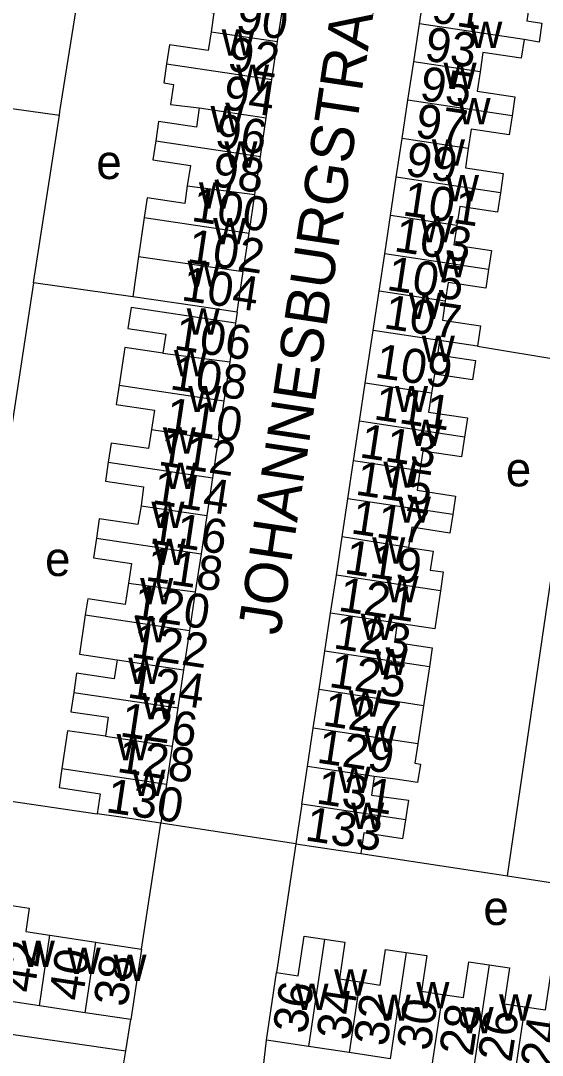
# Model space of a CAD drawing. Extents: x 163012 to 165277, y 382513 to 383987.
# Drawn here: x 163589 to 163650, y 383224 to 383344.9 of the extents above; entities that cross this region are included whole.
import ezdxf

# ---------------------------------------------------------------- set-up
doc = ezdxf.new("R2010")
doc.units = 0
for name, color, linetype in [('BLT_Basislijn', 7, 'Continuous'), ('BLT_Bebouwing', 7, 'Continuous'), ('BLT_Centroide', 7, 'Continuous'), ('BLT_Huisnummer', 7, 'Continuous'), ('BLT_Huisnummer_ tussenligend', 7, 'Continuous'), ('BLT_Onderverdeling_panden', 7, 'Continuous'), ('BLT_Straatnaam', 7, 'Continuous'), ('BLT_Vlakafsluiter', 7, 'Continuous')]:
    doc.layers.add(name, color=color, linetype=linetype)

msp = doc.modelspace()

# ---------------------------------------------------------------- linework, layer by layer
at = {"layer": 'BLT_Basislijn'}
for p, q in [((163578.51, 383335.96), (163593.55, 383333.89)), ((163590.52, 383314.29), (163587.56, 383294.8)), ((163602.12, 383312.65), (163590.52, 383314.29)), ((163614.32, 383310.83), (163614.13, 383309.57)), ((163642.42, 383306.86), (163654.69, 383304.83)), ((163645.91, 383244.93), (163654.69, 383304.83)), ((163581.46, 383254.63), (163597.96, 383252.2)), ((163603.16, 383236.37), (163605.39, 383251.09)), ((163621.19, 383248.7), (163618.94, 383233.65)), ((163628.78, 383247.57), (163645.91, 383244.93)), ((163645.91, 383244.93), (163662.24, 383242.43)), ((163601.31, 383224.5), (163601.91, 383228.14)), ((163617.35, 383222.35), (163617.75, 383225.74)), ((163600.65, 383220.44), (163601.31, 383224.5))]:
    msp.add_line(p, q, dxfattribs=at)
for points in [[(163593.55, 383333.89), (163593.61, 383334.29), (163599.84, 383373.27)], [(163590.52, 383314.29), (163590.56, 383314.53), (163593.55, 383333.89)], [(163553.82, 383235.38), (163553.31, 383231.45), (163601.31, 383224.5)]]:
    msp.add_lwpolyline(points, dxfattribs=at)
at = {"layer": 'BLT_Bebouwing'}
for p, q in [((163635.63, 383344.56), (163636.3, 383349.01)), ((163619.06, 383342.48), (163619.73, 383346.98)), ((163634.96, 383340.11), (163635.63, 383344.56)), ((163618.39, 383338.05), (163619.06, 383342.48)), ((163634.28, 383335.62), (163634.96, 383340.11)), ((163617.72, 383333.55), (163618.39, 383338.05)), ((163633.61, 383331.14), (163634.28, 383335.62)), ((163617.05, 383329.05), (163617.72, 383333.55)), ((163632.93, 383326.63), (163633.61, 383331.14)), ((163616.38, 383324.6), (163617.05, 383329.05)), ((163632.25, 383322.13), (163632.93, 383326.63)), ((163615.71, 383320.09), (163616.38, 383324.6)), ((163631.58, 383317.68), (163632.25, 383322.13)), ((163615.04, 383315.62), (163615.71, 383320.09)), ((163630.92, 383313.29), (163631.58, 383317.68)), ((163614.32, 383310.83), (163615.04, 383315.62)), ((163630.23, 383308.7), (163630.92, 383313.29)), ((163614.13, 383309.57), (163613.45, 383305.03)), ((163629.3, 383302.55), (163630.23, 383308.7)), ((163642.42, 383306.86), (163637.98, 383307.53)), ((163613.45, 383305.03), (163612.77, 383300.48)), ((163628.63, 383298.09), (163629.3, 383302.55)), ((163612.77, 383300.48), (163612.1, 383295.97)), ((163627.93, 383293.48), (163628.63, 383298.09)), ((163612.1, 383295.97), (163611.43, 383291.49)), ((163627.26, 383289.03), (163627.93, 383293.48)), ((163611.43, 383291.49), (163610.77, 383287.07)), ((163626.6, 383284.59), (163627.26, 383289.03)), ((163610.77, 383287.07), (163610.1, 383282.59)), ((163625.92, 383280.09), (163626.6, 383284.59)), ((163610.1, 383282.59), (163609.43, 383278.14)), ((163625.25, 383275.66), (163625.92, 383280.09)), ((163609.43, 383278.14), (163608.76, 383273.62)), ((163624.58, 383271.22), (163625.25, 383275.66)), ((163608.76, 383273.62), (163608.07, 383269.04)), ((163623.91, 383266.75), (163624.58, 383271.22)), ((163608.07, 383269.04), (163607.4, 383264.57)), ((163623.23, 383262.23), (163623.91, 383266.75)), ((163607.4, 383264.57), (163606.74, 383260.11)), ((163636.12, 383264.84), (163635.45, 383260.38)), ((163622.55, 383257.74), (163623.23, 383262.23)), ((163606.74, 383260.11), (163606.07, 383255.67)), ((163621.89, 383253.32), (163622.55, 383257.74)), ((163606.07, 383255.67), (163605.39, 383251.09)), ((163592.44, 383238.01), (163597.8, 383237.19)), ((163603.16, 383236.37), (163601.91, 383228.14)), ((163617.75, 383225.74), (163618.94, 383233.65)), ((163591.2, 383229.75), (163585.85, 383230.56)), ((163596.56, 383228.95), (163591.2, 383229.75)), ((163601.91, 383228.14), (163596.56, 383228.95)), ((163622.65, 383225), (163617.75, 383225.74)), ((163627.42, 383224.28), (163622.65, 383225)), ((163632.21, 383223.56), (163627.42, 383224.28))]:
    msp.add_line(p, q, dxfattribs=at)
for points in [[(163607.44, 383348.82), (163607.09, 383346.52), (163611.61, 383345.85), (163611.28, 383343.64)], [(163644, 383347.85), (163648.55, 383347.23), (163648.19, 383344.9), (163649.93, 383344.64), (163649.64, 383342.42), (163647.86, 383342.72)], [(163611.28, 383343.64), (163610.95, 383341.44), (163606.41, 383342.12), (163606.08, 383339.89)], [(163647.86, 383342.72), (163647.53, 383340.53), (163643.06, 383341.2), (163642.72, 383338.94)], [(163606.08, 383339.89), (163605.74, 383337.65), (163606.88, 383337.48), (163606.53, 383335.13), (163609.9, 383334.72)], [(163642.72, 383338.94), (163642.38, 383336.67), (163646.79, 383336.01), (163646.46, 383333.79)], [(163609.9, 383334.72), (163609.56, 383332.46), (163605.13, 383333.12), (163604.8, 383330.88)], [(163646.46, 383333.79), (163646.12, 383331.57), (163641.69, 383332.24), (163641.35, 383329.97)], [(163604.8, 383330.88), (163604.46, 383328.64), (163608.86, 383327.98), (163608.5, 383325.61)], [(163641.35, 383329.97), (163641.01, 383327.71), (163645.43, 383327.04), (163645.1, 383324.8)], [(163608.5, 383325.61), (163608.2, 383323.57), (163603.79, 383324.23), (163603.44, 383321.93)], [(163645.1, 383324.8), (163644.76, 383322.55), (163640.35, 383323.22), (163640.01, 383320.96)], [(163603.44, 383321.93), (163602.79, 383317.37)], [(163640.01, 383320.96), (163639.67, 383318.71), (163644.05, 383318.05), (163643.71, 383315.85)], [(163602.79, 383317.37), (163602.12, 383312.65)], [(163643.71, 383315.85), (163643.38, 383313.64), (163638.98, 383314.31), (163638.65, 383312.12)], [(163614.32, 383310.83), (163609.38, 383311.57), (163602.12, 383312.65)], [(163614.13, 383309.57), (163609.19, 383310.31), (163601.93, 383311.4), (163601.56, 383308.95), (163605.97, 383308.29), (163605.64, 383306.07)], [(163638.65, 383312.12), (163638.33, 383309.93), (163642.78, 383309.26), (163642.42, 383306.86)], [(163605.64, 383306.07), (163601.19, 383306.73), (163600.52, 383302.31)], [(163637.98, 383307.53), (163637.73, 383305.87), (163642.17, 383305.2), (163641.83, 383302.94), (163637.39, 383303.61), (163637.05, 383301.39)], [(163600.52, 383302.31), (163600.19, 383300.05), (163604.65, 383299.39), (163604.32, 383297.14)], [(163637.05, 383301.39), (163636.71, 383299.17), (163641.25, 383298.48), (163641.17, 383297.99), (163640.89, 383296.25)], [(163604.32, 383297.14), (163603.98, 383294.89), (163599.58, 383295.54), (163599.25, 383293.32)], [(163640.89, 383296.25), (163640.54, 383293.92), (163636.04, 383294.6), (163635.69, 383292.31)], [(163599.25, 383293.32), (163598.92, 383291.09), (163603.39, 383290.42), (163603.1, 383288.22)], [(163635.69, 383292.31), (163635.35, 383290.02), (163639.84, 383289.34), (163639.52, 383287.18)], [(163603.1, 383288.22), (163602.7, 383286.03), (163598.21, 383286.7), (163597.87, 383284.42)], [(163639.52, 383287.18), (163639.19, 383285.02), (163634.73, 383285.7), (163634.37, 383283.33)], [(163597.87, 383284.42), (163597.53, 383282.13), (163601.98, 383281.47), (163601.62, 383279.17)], [(163634.37, 383283.33), (163637.23, 383282.9), (163636.9, 383280.7), (163638.42, 383280.47), (163638.08, 383278.26)], [(163601.62, 383279.17), (163601.24, 383276.67), (163596.85, 383277.33), (163596.57, 383275.45)], [(163638.08, 383278.26), (163637.42, 383273.81), (163633.04, 383274.49)], [(163596.57, 383275.45), (163595.88, 383270.87), (163600.28, 383270.21)], [(163633.04, 383274.49), (163632.7, 383272.26), (163637.14, 383271.6), (163636.81, 383269.38)], [(163600.28, 383270.21), (163599.94, 383267.99), (163595.55, 383268.65), (163595.22, 383266.39)], [(163636.81, 383269.38), (163636.12, 383264.84)], [(163595.22, 383266.39), (163594.88, 383264.14), (163599.26, 383263.49), (163598.92, 383261.28)], [(163598.92, 383261.28), (163594.49, 383261.91), (163593.83, 383257.5)], [(163635.45, 383260.38), (163635.11, 383258.11), (163635.75, 383258.02), (163635.42, 383255.85), (163632.83, 383256.23), (163630.35, 383256.57)], [(163593.83, 383257.5), (163593.5, 383255.27), (163598.32, 383254.55), (163597.96, 383252.2)], [(163630.35, 383256.57), (163630.35, 383256.57), (163630.03, 383254.39), (163634.35, 383253.78), (163634, 383251.49)], [(163621.89, 383253.32), (163621.39, 383250), (163621.19, 383248.7)], [(163605.39, 383251.09), (163600.44, 383251.83), (163597.96, 383252.2)], [(163634, 383251.49), (163633.67, 383249.28), (163629.15, 383249.96), (163628.78, 383247.57)], [(163621.19, 383248.7), (163626.14, 383247.96), (163628.78, 383247.57)], [(163587.09, 383238.83), (163587.47, 383241.56), (163590.02, 383241.17), (163589.61, 383238.44), (163592.44, 383238.01)], [(163618.94, 383233.65), (163621.47, 383233.27), (163622.17, 383237.89), (163624.54, 383237.53)], [(163597.8, 383237.19), (163598.22, 383237.12), (163603.16, 383236.37)], [(163624.54, 383237.53), (163626.92, 383237.18), (163626.29, 383232.89), (163628.66, 383232.54)], [(163628.66, 383232.54), (163631.04, 383232.18), (163631.66, 383236.35), (163634.08, 383235.99)], [(163634.08, 383235.99), (163636.5, 383235.62), (163635.88, 383231.46), (163638.33, 383231.09)], [(163638.33, 383231.09), (163640.77, 383230.72), (163641.41, 383234.91), (163643.8, 383234.55)], [(163643.8, 383234.55), (163646.18, 383234.19), (163645.55, 383229.99), (163647.96, 383229.63)], [(163647.96, 383229.63), (163650.36, 383229.27), (163650.99, 383233.42), (163653.43, 383233.05)]]:
    msp.add_lwpolyline(points, dxfattribs=at)
at = {"layer": 'BLT_Onderverdeling_panden'}
for p, q in [((163647.86, 383342.72), (163635.63, 383344.56)), ((163611.28, 383343.64), (163619.06, 383342.48)), ((163606.08, 383339.89), (163618.39, 383338.05)), ((163642.72, 383338.94), (163634.96, 383340.11)), ((163646.46, 383333.79), (163634.28, 383335.62)), ((163609.9, 383334.72), (163617.72, 383333.55)), ((163604.8, 383330.88), (163617.05, 383329.05)), ((163641.35, 383329.97), (163633.61, 383331.14)), ((163645.1, 383324.8), (163632.93, 383326.63)), ((163608.5, 383325.61), (163616.38, 383324.6)), ((163603.44, 383321.93), (163615.71, 383320.09)), ((163640.01, 383320.96), (163632.25, 383322.13)), ((163643.71, 383315.85), (163631.58, 383317.68)), ((163602.79, 383317.37), (163615.04, 383315.62)), ((163638.65, 383312.12), (163630.92, 383313.29)), ((163637.98, 383307.53), (163630.23, 383308.7)), ((163605.64, 383306.07), (163613.45, 383305.03)), ((163600.52, 383302.31), (163612.77, 383300.48)), ((163637.05, 383301.39), (163629.3, 383302.55)), ((163640.89, 383296.25), (163628.63, 383298.09)), ((163604.32, 383297.14), (163612.1, 383295.97)), ((163599.25, 383293.32), (163611.43, 383291.49)), ((163635.69, 383292.31), (163627.93, 383293.48)), ((163639.52, 383287.18), (163627.26, 383289.03)), ((163603.1, 383288.22), (163610.77, 383287.07)), ((163597.87, 383284.42), (163610.1, 383282.59)), ((163634.37, 383283.33), (163626.6, 383284.59)), ((163638.08, 383278.26), (163625.92, 383280.09)), ((163601.62, 383279.17), (163609.43, 383278.14)), ((163596.57, 383275.45), (163608.76, 383273.62)), ((163633.04, 383274.49), (163625.25, 383275.66)), ((163636.81, 383269.38), (163624.58, 383271.22)), ((163600.28, 383270.21), (163608.07, 383269.04)), ((163636.12, 383264.84), (163623.91, 383266.75)), ((163595.22, 383266.39), (163607.4, 383264.57)), ((163635.45, 383260.38), (163623.23, 383262.23)), ((163598.92, 383261.28), (163606.74, 383260.11)), ((163593.83, 383257.5), (163606.07, 383255.67)), ((163630.35, 383256.57), (163622.55, 383257.74)), ((163634, 383251.49), (163621.89, 383253.32)), ((163591.2, 383229.75), (163592.44, 383238.01)), ((163596.56, 383228.95), (163597.8, 383237.19)), ((163624.54, 383237.53), (163622.65, 383225)), ((163634.08, 383235.99), (163632.21, 383223.56)), ((163643.8, 383234.55), (163641.92, 383222.1)), ((163628.66, 383232.54), (163627.42, 383224.28)), ((163638.33, 383231.09), (163637.08, 383222.83)), ((163647.96, 383229.63), (163646.72, 383221.38))]:
    msp.add_line(p, q, dxfattribs=at)
at = {"layer": 'BLT_Vlakafsluiter'}
msp.add_line((163621.19, 383248.7), (163605.39, 383251.09), dxfattribs=at)

# ---------------------------------------------------------------- texts
at = {"layer": 'BLT_Centroide'}
for s, p in [('w', (163641.46, 383341.75)), ('w', (163612.52, 383340.84)), ('w', (163614.2, 383336.72)), ('w', (163638.45, 383336.94)), ('w', (163640.09, 383332.81)), ('w', (163611.21, 383331.88)), ('w', (163612.83, 383327.75)), ('w', (163637.09, 383327.97)), ('e', (163597.86, 383326.41)), ('w', (163609.86, 383322.94)), ('w', (163638.73, 383323.81)), ('w', (163611.52, 383318.78)), ('w', (163635.74, 383319)), ('w', (163637.37, 383314.91)), ('w', (163608.52, 383313.81)), ('w', (163634.39, 383310.06)), ('w', (163608.43, 383308.22)), ('w', (163635.91, 383305.03)), ('w', (163606.94, 383303.34)), ('w', (163608.6, 383299.16)), ('w', (163632.78, 383299.16)), ('w', (163634.46, 383295.19)), ('w', (163605.63, 383294.31)), ('w', (163605.77, 383290.19)), ('w', (163631.42, 383290.31)), ('e', (163645.73, 383290.48)), ('w', (163604.3, 383285.62)), ('w', (163633.11, 383286.22)), ('w', (163604.46, 383281.28)), ('w', (163630.11, 383281.44)), ('e', (163591.87, 383280)), ('w', (163631.67, 383276.94)), ('w', (163602.98, 383276.69)), ('w', (163602.32, 383272.25)), ('w', (163628.77, 383272.53)), ('w', (163630.41, 383268.41)), ('w', (163601.59, 383267.38)), ('w', (163627.38, 383263.56)), ('w', (163603.21, 383263.25)), ('w', (163629.05, 383259.41)), ('w', (163600.23, 383258.47)), ('w', (163602.08, 383254.28)), ('w', (163626.07, 383254.62)), ('w', (163627.65, 383250.44)), ('e', (163643.11, 383239.2)), ('w', (163589.14, 383234.28)), ('w', (163594.5, 383233.47)), ('w', (163599.86, 383232.66)), ('w', (163625.66, 383230.95)), ('w', (163621.14, 383229.27)), ('w', (163635.27, 383229.45)), ('w', (163630.75, 383228)), ('w', (163644.94, 383228.02)), ('w', (163640.44, 383226.55))]:
    msp.add_text(s, height=4, dxfattribs=at).set_placement(p)
at = {"layer": 'BLT_Huisnummer'}
for s, rotation, p in [('91', 351.4353, (163636.9, 383344.76)), ('92', 351.4969, (163613.04, 383339.14)), ('95', 351.4361, (163635.53, 383335.68)), ('96', 351.5001, (163611.58, 383330.15)), ('99', 351.4241, (163633.85, 383326.85)), ('100', 351.5001, (163608.86, 383321.53)), ('103', 351.4335, (163632.56, 383317.99)), ('104', 351.4874, (163607.69, 383312.26)), ('107', 351.4432, (163631.34, 383308.99)), ('108', 351.4876, (163606.35, 383301.86)), ('111', 351.4432, (163630.18, 383298.34)), ('112', 351.4923, (163604.99, 383292.99)), ('115', 351.4363, (163628.03, 383289.53)), ('116', 351.4961, (163604, 383283.84)), ('119', 351.4252, (163626.74, 383280.33)), ('120', 351.4948, (163601.97, 383275.07)), ('123', 351.4297, (163625.46, 383271.57)), ('124', 351.4976, (163601.37, 383265.81)), ('127', 351.4373, (163624.21, 383262.55)), ('130', 351.5004, (163598.86, 383252.42)), ('133', 351.5699, (163622.14, 383249.11)), ('42', 81.4387, (163590.59, 383231.15)), ('38', 81.3072, (163601.45, 383229.52)), ('36', 81.4448, (163622.42, 383226.37)), ('30', 81.442, (163636.9, 383224.38)), ('26', 81.4421, (163646.38, 383223.05))]:
    msp.add_text(s, height=4, rotation=rotation, dxfattribs=at).set_placement(p)
at = {"layer": 'BLT_Huisnummer_ tussenligend'}
for s, rotation, p in [('90', 351.4984, (163614.05, 383343.57)), ('93', 351.4353, (163636.1, 383340.3)), ('94', 351.4969, (163612.5, 383334.62)), ('97', 351.4361, (163635, 383331.33)), ('98', 351.5001, (163611.24, 383325.63)), ('101', 351.4241, (163633.55, 383322.2)), ('102', 351.5001, (163608.35, 383316.65)), ('105', 351.4335, (163631.69, 383313.47)), ('106', 351.4874, (163606.82, 383306.52)), ('109', 351.4432, (163630.3, 383303.25)), ('110', 351.4876, (163605.76, 383296.95)), ('113', 351.4432, (163628.52, 383293.89)), ('114', 351.4923, (163604.28, 383288.47)), ('117', 351.4363, (163627.5, 383285.01)), ('118', 351.4961, (163603.49, 383279.49)), ('121', 351.4252, (163626.03, 383275.95)), ('122', 351.4948, (163601.81, 383270.54)), ('125', 351.4297, (163624.94, 383267.05)), ('126', 351.4976, (163600.5, 383261.29)), ('129', 351.4373, (163623.52, 383258.2)), ('128', 351.4976, (163600.16, 383257.11)), ('131', 351.4373, (163623.45, 383253.43)), ('40', 81.3072, (163596.23, 383230.21)), ('34', 81.442, (163627.51, 383225.6)), ('32', 81.442, (163631.86, 383224.91)), ('28', 81.4421, (163641.86, 383223.75)), ('24', 81.4371, (163651.35, 383222.27))]:
    msp.add_text(s, height=4, rotation=rotation, dxfattribs=at).set_placement(p)
at = {"layer": 'BLT_Straatnaam'}
msp.add_text('JOHANNESBURGSTRAAT', height=5, rotation=81.4629, dxfattribs=at).set_placement((163619.34, 383272.95))

doc.saveas('drawing.dxf')
